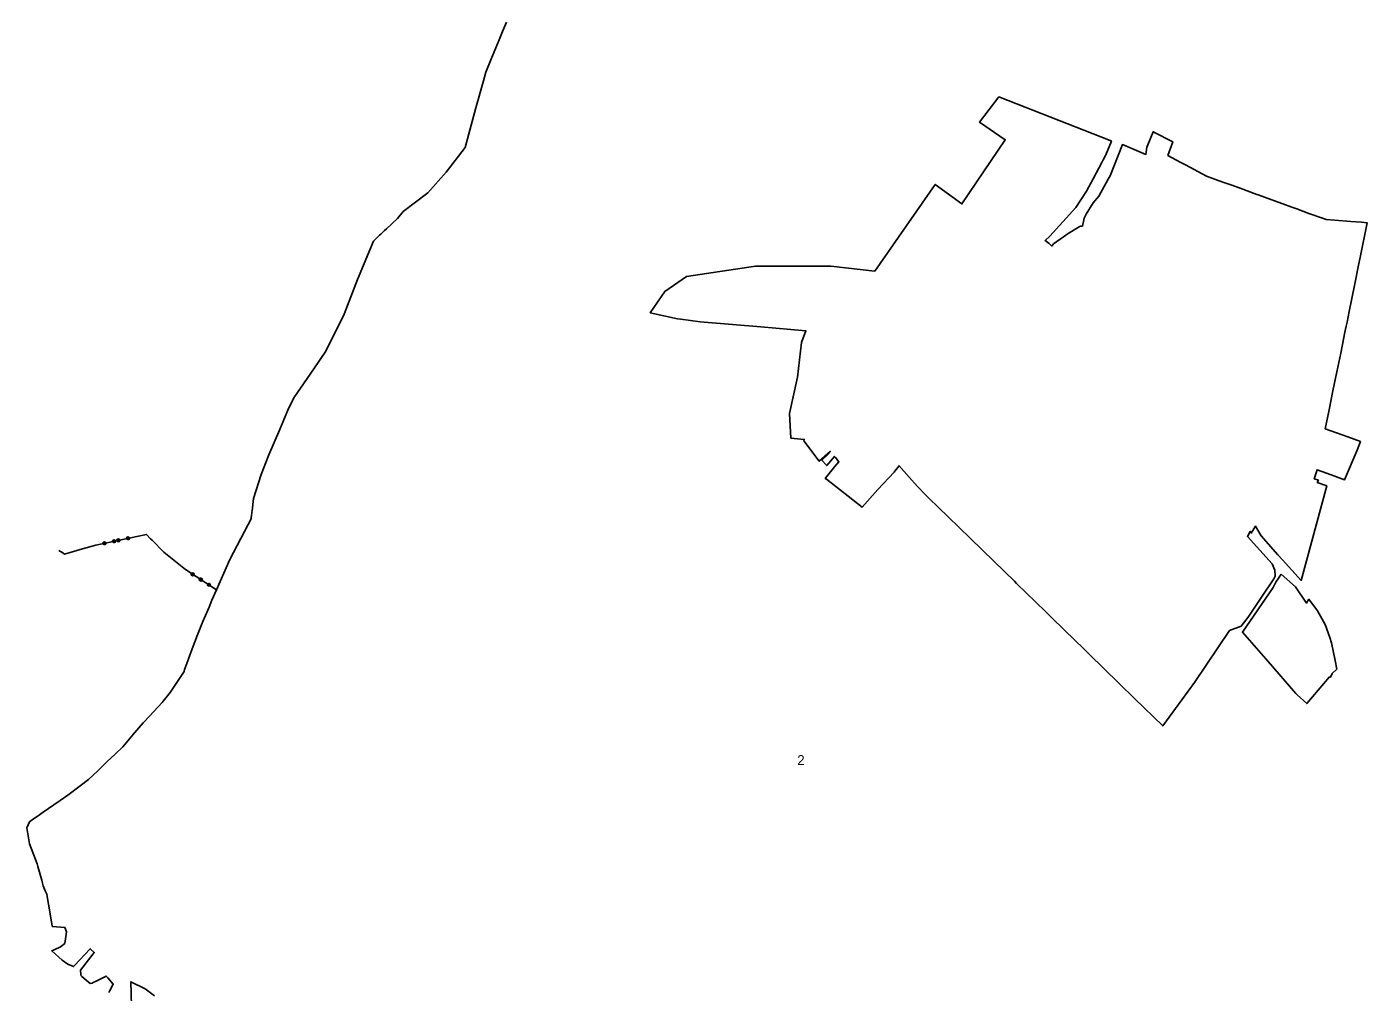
# Model space of a CAD drawing. Extents: x -738273 to -735126, y -1127782 to -1123636.
# Drawn here: x -738183 to -736497, y -1126567 to -1125353 of the extents above; entities that cross this region are included whole.
import ezdxf

# ---------------------------------------------------------------- set-up
doc = ezdxf.new("R2010")
doc.units = 0
for name, color, linetype in [('HRA_KU', 7, 'Continuous'), ('Level 255', 7, 'Continuous'), ('OVNE_PRE', 7, 'Continuous'), ('OVNE_SET', 7, 'Continuous'), ('OVNI_SET', 7, 'Continuous'), ('OZN', 7, 'Continuous')]:
    doc.layers.add(name, color=color, linetype=linetype)

msp = doc.modelspace()

# ---------------------------------------------------------------- linework, layer by layer
at = {"layer": 'HRA_KU'}
for points in [[(-737944.6, -1126061.2), (-737983.8, -1126035.8), (-738011, -1126013.8), (-738025.7, -1125998.9), (-738027.5, -1125997.1), (-738032.7, -1125991.6), (-738044.7, -1125994.1), (-738096.6, -1126004.9), (-738113.4, -1126009.8), (-738136.1, -1126016.3), (-738138, -1126014.8), (-738143, -1126011.7)], [(-738073.9, -1126001.8), (-738075, -1126001.1), (-738075.3, -1125999.7), (-738074.6, -1125998.6), (-738073.2, -1125998.3), (-738072.1, -1125999.1), (-738071.8, -1126000.4), (-738072.6, -1126001.5), (-738073.9, -1126001.8), (-738073.9, -1126001.6), (-738072.7, -1126001.3), (-738072.4, -1126000.9), (-738074.4, -1126001.3), (-738074.8, -1126001), (-738072.1, -1126000.4), (-738072.2, -1126000), (-738074.9, -1126000.6), (-738075, -1126000.2), (-738072.2, -1125999.6), (-738072.3, -1125999.2), (-738075.1, -1125999.8), (-738074.8, -1125999.3), (-738072.8, -1125998.9), (-738073.3, -1125998.6), (-738074.5, -1125998.8)], [(-738068.5, -1126000.7), (-738069.6, -1125999.9), (-738069.9, -1125998.6), (-738069.2, -1125997.5), (-738067.8, -1125997.2), (-738066.7, -1125997.9), (-738066.4, -1125999.3), (-738067.2, -1126000.4), (-738068.5, -1126000.7), (-738068.4, -1126000.4), (-738067.2, -1126000.2), (-738066.9, -1125999.7), (-738068.9, -1126000.1), (-738069.3, -1125999.8), (-738066.6, -1125999.3), (-738066.7, -1125998.9), (-738069.4, -1125999.4), (-738069.5, -1125999), (-738066.8, -1125998.5), (-738066.8, -1125998.1), (-738069.6, -1125998.6), (-738069.3, -1125998.2), (-738067.3, -1125997.8), (-738067.8, -1125997.5), (-738069, -1125997.7)], [(-738056.3, -1125998.1), (-738057.4, -1125997.4), (-738057.7, -1125996.1), (-738056.9, -1125994.9), (-738055.6, -1125994.7), (-738054.5, -1125995.4), (-738054.2, -1125996.7), (-738054.9, -1125997.8), (-738056.3, -1125998.1), (-738056.2, -1125997.9), (-738055.1, -1125997.7), (-738054.8, -1125997.2), (-738056.7, -1125997.6), (-738057.2, -1125997.3), (-738054.5, -1125996.7), (-738054.5, -1125996.3), (-738057.3, -1125996.9), (-738057.4, -1125996.5), (-738054.6, -1125995.9), (-738054.7, -1125995.5), (-738057.4, -1125996.1), (-738057.1, -1125995.6), (-738055.2, -1125995.2), (-738055.6, -1125994.9), (-738056.8, -1125995.2)], [(-738086.1, -1126004.4), (-738087.2, -1126003.6), (-738087.5, -1126002.3), (-738086.8, -1126001.2), (-738085.5, -1126000.9), (-738084.3, -1126001.6), (-738084.1, -1126003), (-738084.8, -1126004.1), (-738086.1, -1126004.4), (-738086, -1126004.1), (-738084.8, -1126003.9), (-738084.5, -1126003.4), (-738086.5, -1126003.8), (-738087, -1126003.5), (-738084.2, -1126002.9), (-738084.3, -1126002.5), (-738087, -1126003.1), (-738087.1, -1126002.7), (-738084.4, -1126002.2), (-738084.5, -1126001.8), (-738087.2, -1126002.3), (-738086.9, -1126001.9), (-738084.9, -1126001.4), (-738085.4, -1126001.1), (-738086.6, -1126001.4)], [(-737976, -1126042.8), (-737976.3, -1126041.5), (-737975.6, -1126040.3), (-737974.3, -1126040), (-737973.1, -1126040.8), (-737972.8, -1126042.1), (-737973.6, -1126043.2), (-737974.9, -1126043.5), (-737976, -1126042.8), (-737975.8, -1126042.7), (-737974.8, -1126043.3), (-737974.2, -1126043.2), (-737975.9, -1126042.1), (-737976, -1126041.6), (-737973.7, -1126043.1), (-737973.5, -1126042.8), (-737975.8, -1126041.2), (-737975.6, -1126040.9), (-737973.2, -1126042.4), (-737973, -1126042.1), (-737975.4, -1126040.6), (-737974.8, -1126040.4), (-737973.1, -1126041.5), (-737973.3, -1126041), (-737974.3, -1126040.3)], [(-737966.1, -1126049.1), (-737966.4, -1126047.8), (-737965.7, -1126046.7), (-737964.4, -1126046.4), (-737963.2, -1126047.1), (-737963, -1126048.5), (-737963.7, -1126049.6), (-737965, -1126049.9), (-737966.1, -1126049.1), (-737965.9, -1126049.1), (-737964.9, -1126049.7), (-737964.3, -1126049.6), (-737966, -1126048.5), (-737966.1, -1126048), (-737963.8, -1126049.5), (-737963.6, -1126049.1), (-737965.9, -1126047.6), (-737965.7, -1126047.3), (-737963.4, -1126048.8), (-737963.1, -1126048.5), (-737965.5, -1126046.9), (-737964.9, -1126046.8), (-737963.3, -1126047.9), (-737963.4, -1126047.4), (-737964.4, -1126046.7)], [(-737965.5, -1126049.5), (-737965.8, -1126048.2), (-737965.1, -1126047.1), (-737963.8, -1126046.8), (-737962.6, -1126047.5), (-737962.3, -1126048.9), (-737963.1, -1126050), (-737964.4, -1126050.3), (-737965.5, -1126049.5), (-737965.4, -1126049.4), (-737964.4, -1126050.1), (-737963.8, -1126049.9), (-737965.5, -1126048.8), (-737965.6, -1126048.3), (-737963.3, -1126049.8), (-737963, -1126049.5), (-737965.4, -1126048), (-737965.2, -1126047.6), (-737962.8, -1126049.1), (-737962.6, -1126048.8), (-737965, -1126047.3), (-737964.4, -1126047.2), (-737962.7, -1126048.2), (-737962.8, -1126047.7), (-737963.8, -1126047)], [(-737955.6, -1126055.9), (-737955.9, -1126054.6), (-737955.2, -1126053.5), (-737953.9, -1126053.2), (-737952.7, -1126053.9), (-737952.5, -1126055.2), (-737953.2, -1126056.4), (-737954.5, -1126056.6), (-737955.6, -1126055.9), (-737955.5, -1126055.8), (-737954.5, -1126056.4), (-737953.9, -1126056.3), (-737955.6, -1126055.2), (-737955.7, -1126054.7), (-737953.4, -1126056.2), (-737953.2, -1126055.8), (-737955.5, -1126054.3), (-737955.3, -1126054), (-737952.9, -1126055.5), (-737952.7, -1126055.2), (-737955.1, -1126053.7), (-737954.5, -1126053.5), (-737952.8, -1126054.6), (-737953, -1126054.1), (-737954, -1126053.4)]]:
    msp.add_lwpolyline(points, dxfattribs=at)
at = {"layer": 'Level 255'}
msp.add_line((-737178.5, -1125909.5), (-737178.5, -1125909.5), dxfattribs=at)
at = {"layer": 'OVNE_PRE'}
for points in [[(-737944.6, -1126061.2), (-737950.3, -1126074.4), (-737954, -1126082.9), (-737960.2, -1126097.1), (-737961.1, -1126099.1), (-737969.5, -1126119.8), (-737970, -1126121.2), (-737974, -1126132.2), (-737978.1, -1126143.4), (-737981.9, -1126154.1), (-737984.7, -1126161.6), (-737985.4, -1126163.8), (-737994.7, -1126177.9), (-738002.9, -1126190.5), (-738011.6, -1126201.2), (-738013.1, -1126203.1), (-738023.5, -1126214.2), (-738035.5, -1126227.1), (-738037.1, -1126228.7), (-738050.3, -1126244.2), (-738051.5, -1126245.6), (-738062.6, -1126258.6), (-738072.3, -1126267.9), (-738082.1, -1126277.3), (-738094.1, -1126288.9), (-738105.7, -1126299.9), (-738116.4, -1126307.9), (-738131.9, -1126319.6), (-738141.5, -1126326.2), (-738149.5, -1126331.9), (-738162.8, -1126341.1), (-738165.5, -1126343), (-738167.3, -1126344.3), (-738176.6, -1126350.8), (-738179.9, -1126353.1), (-738183.3, -1126360.7), (-738181.1, -1126373.4), (-738179.8, -1126380.8), (-738170.2, -1126405.9), (-738169.3, -1126409.1), (-738164.6, -1126426.3), (-738163.6, -1126430.4), (-738162.6, -1126433.8), (-738162.1, -1126435.8), (-738160.3, -1126439.8), (-738158.3, -1126444), (-738156.9, -1126452.2), (-738156.1, -1126456.5), (-738151.3, -1126483.8), (-738151.1, -1126484.9), (-738135.4, -1126485.9), (-738133.3, -1126491.3), (-738135.4, -1126506.1), (-738140.8, -1126510.3), (-738148.8, -1126514.1), (-738151.9, -1126515.5), (-738138.7, -1126527.1), (-738131.9, -1126532.3), (-738124.4, -1126535.2), (-738123.3, -1126534), (-738103.4, -1126512.7), (-738098.4, -1126517.4), (-738115.8, -1126539.9), (-738115.2, -1126545), (-738115, -1126546.8), (-738114.1, -1126547.6), (-738108.8, -1126552.2), (-738103.8, -1126556.4), (-738101.2, -1126556.2), (-738099.8, -1126555.4), (-738096.1, -1126553.6), (-738083.4, -1126547.2), (-738081.4, -1126549.4), (-738074.5, -1126557.2), (-738078.9, -1126565.2), (-738080.3, -1126567.7)], [(-738051.4, -1126584), (-738052.3, -1126554.4), (-738034.6, -1126563.3), (-738022.7, -1126572.2)]]:
    msp.add_lwpolyline(points, dxfattribs=at)
at = {"layer": 'OVNE_SET'}
msp.add_lwpolyline([(-737579.8, -1125347.1), (-737584.7, -1125358.9), (-737589, -1125369.4), (-737599.4, -1125394.4), (-737605.8, -1125409.8), (-737608.8, -1125421), (-737618.1, -1125454.7), (-737631.9, -1125504.9), (-737655.8, -1125535.8), (-737678.8, -1125561.6), (-737709.7, -1125585.4), (-737716.9, -1125594.1), (-737730.7, -1125607), (-737733.1, -1125609.2), (-737737.7, -1125613.6), (-737739.5, -1125615.2), (-737747, -1125622.4), (-737767, -1125670.6), (-737784.1, -1125714.4), (-737807, -1125761), (-737822.2, -1125783.1), (-737838.9, -1125807.4), (-737847.4, -1125819.8), (-737854.8, -1125835.1), (-737865.5, -1125860.4), (-737878.6, -1125891.3), (-737888.4, -1125916), (-737898, -1125946.4), (-737899.9, -1125961.8), (-737900.1, -1125963.7), (-737900.7, -1125968.7), (-737900.8, -1125969.1), (-737901.1, -1125972), (-737904.8, -1125978.9), (-737927.9, -1126023), (-737935.4, -1126040.2), (-737944.6, -1126061.2)], dxfattribs=at)
at = {"layer": 'OVNI_SET'}
for points in [[(-737165.8, -1125894.6), (-737167, -1125893.3), (-737176.7, -1125904.9), (-737177.4, -1125904.1), (-737183, -1125898.1), (-737175.1, -1125890.8), (-737172.1, -1125887.3), (-737172.3, -1125887.1), (-737175.7, -1125890), (-737186.1, -1125899.4), (-737205.6, -1125873.7), (-737205, -1125872), (-737221.8, -1125870.4), (-737223.5, -1125839.2), (-737213.5, -1125793.7), (-737208.3, -1125750), (-737202.9, -1125735.3), (-737259.8, -1125730.4), (-737335.8, -1125724.2), (-737360.2, -1125720.8), (-737364.3, -1125720.4), (-737398.8, -1125712.7), (-737380.5, -1125685.8), (-737353.2, -1125666.9), (-737266.4, -1125653.9), (-737171.6, -1125653.9), (-737116.3, -1125660.5), (-737040.1, -1125551.2), (-737006.5, -1125575.7), (-736952, -1125495), (-736984.5, -1125472.8), (-736960.1, -1125441.1), (-736819.8, -1125496), (-736818.5, -1125496.6), (-736825.6, -1125514), (-736826, -1125514.8), (-736828.6, -1125520.2), (-736830.5, -1125523.7), (-736841.6, -1125544.3), (-736849.8, -1125559.5), (-736863.4, -1125580.3), (-736896.1, -1125616.1), (-736901.8, -1125621.7), (-736896.9, -1125625.7), (-736893.6, -1125628.7), (-736891.3, -1125626), (-736878.7, -1125617.1), (-736872.8, -1125612.9), (-736858.9, -1125604.6), (-736857.3, -1125603.7), (-736856.2, -1125603.7), (-736855, -1125603.7), (-736852.8, -1125593.6), (-736850, -1125588.5), (-736841.5, -1125574.5), (-736834.3, -1125566), (-736822.6, -1125544.6), (-736820, -1125540.2), (-736804.6, -1125501), (-736775, -1125513.5), (-736773.9, -1125504.3), (-736772.6, -1125501.2), (-736765.9, -1125484.9), (-736741.1, -1125497.8), (-736747.4, -1125514.7), (-736731.8, -1125523), (-736725, -1125526.6), (-736698.6, -1125540.7), (-736678.1, -1125548.2), (-736666.8, -1125552.3), (-736656.5, -1125556.1), (-736635.3, -1125563.8), (-736633.7, -1125564.4), (-736613, -1125571.9), (-736602.6, -1125575.6), (-736591.4, -1125579.7), (-736585.3, -1125581.9), (-736569.8, -1125587.6), (-736553, -1125593.7), (-736548.2, -1125595.4), (-736537.9, -1125596.2), (-736517.3, -1125597.7), (-736503.7, -1125598.7), (-736496.6, -1125599.3), (-736505.4, -1125643), (-736507.4, -1125652.8), (-736512.2, -1125676.4), (-736519.1, -1125711), (-736521.9, -1125724.5), (-736522.8, -1125729.4), (-736524.5, -1125737.2), (-736529.9, -1125763.3), (-736534.7, -1125787), (-736539.6, -1125810.7), (-736544.5, -1125834.6), (-736549.3, -1125858.6), (-736521.1, -1125868.8), (-736505, -1125874.7), (-736509.2, -1125885.4), (-736525, -1125922.8), (-736541.8, -1125916.7), (-736559.7, -1125910.2), (-736563.2, -1125921.5), (-736558, -1125923.4), (-736559.3, -1125926.1), (-736547.4, -1125930.5), (-736579.8, -1126049.3), (-736603.3, -1126023.5), (-736608.8, -1126017.4), (-736630, -1125993.3), (-736637.3, -1125981.1), (-736642.4, -1125989.9), (-736643.8, -1125987.8), (-736647.2, -1125994.1), (-736616.2, -1126028.4), (-736612.7, -1126036.4), (-736612.5, -1126044.2), (-736613.9, -1126047.4), (-736630.5, -1126071.8), (-736646.3, -1126095.8), (-736655.3, -1126106.9), (-736669.8, -1126112.5), (-736713.7, -1126178), (-736753.8, -1126232.5), (-736789.3, -1126197.8), (-736827.8, -1126160.4), (-736835.2, -1126153.1), (-736839.3, -1126149.2), (-736852.9, -1126135.9), (-736877.6, -1126111.9), (-736894.2, -1126095.6), (-736901.5, -1126088.6), (-736937.8, -1126053.2), (-736940.6, -1126050.5), (-736966.1, -1126025.6), (-736996, -1125996.4), (-737023.8, -1125969.4), (-737048.1, -1125945.7), (-737054.7, -1125939.3), (-737059.7, -1125934), (-737062.3, -1125931.2), (-737073, -1125919.4), (-737085.7, -1125905.2), (-737090.9, -1125912), (-737091.9, -1125913.1), (-737112.4, -1125935.2), (-737132.3, -1125957.1), (-737177.1, -1125922.2), (-737178.5, -1125921.1), (-737167.1, -1125906.6), (-737161.3, -1125900.2), (-737165.8, -1125894.6)], [(-736604.7, -1126041.4), (-736586.8, -1126057.3), (-736573, -1126077.9), (-736569.8, -1126073.1), (-736559.1, -1126087.5), (-736549.3, -1126104.8), (-736543.5, -1126121), (-736541.5, -1126128), (-736536.8, -1126150.1), (-736534.7, -1126161), (-736540.6, -1126166.7), (-736542.6, -1126171.3), (-736543.8, -1126170.8), (-736572.6, -1126204.3), (-736584.7, -1126193.5), (-736586.2, -1126191.8), (-736621.3, -1126151.5), (-736653.6, -1126114.3), (-736614.9, -1126058.3), (-736611.6, -1126051.7), (-736604.7, -1126041.4)]]:
    msp.add_lwpolyline(points, dxfattribs=at)

# ---------------------------------------------------------------- texts
at = {"layer": 'OZN'}
msp.add_text('2', height=12.5, dxfattribs=at).set_placement((-737213.8, -1126281.7))

doc.saveas('drawing.dxf')
